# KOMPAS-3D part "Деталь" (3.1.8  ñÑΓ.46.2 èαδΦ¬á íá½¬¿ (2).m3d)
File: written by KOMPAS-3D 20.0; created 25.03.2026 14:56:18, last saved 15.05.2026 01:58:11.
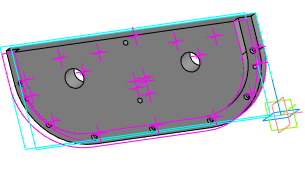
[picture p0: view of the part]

Document properties: Автор: TMK; Полное имя файла: E:\test_kompas\all_v18\3.1.8  дет.46.2 Крышка балки (2).m3d; Организация: TMK

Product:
- Part/product: Деталь
    Масса: 21.9342
  - Body: Тело 3
  - Body: Тело 1

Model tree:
1. Операция без истории:1
2. Эскиз:1
3. Смещенная плоскость:1  (with: Операция без истории:1)
4. Эскиз:2
5. Смещенная плоскость:2  (with: Операция без истории:1)
6. Эскиз:3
